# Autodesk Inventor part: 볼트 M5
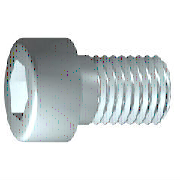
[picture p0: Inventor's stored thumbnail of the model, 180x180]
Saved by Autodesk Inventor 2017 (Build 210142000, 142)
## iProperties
IsCustomPart: 1
Created: 2012-02
Part Number: 볼트 M5
Material: 강철, 연강
Description: 6각머리 태핑 나사
Document SubType Name: Modeling
Standard: KS B 1003
Designer: mduedu
Standards Organization: KS
Language: ko-KR
Size Designation: M 5 x 12
Categories: <MemberInstance><Categories><Category DisplayName="조임쇠" InternalName="e4da775c-781d-43d5-af7c-5136215cf5a6" Mnemonic="FSTN"><Category DisplayName="볼트" InternalN
Density: 1 g/cm^3
Appearance: 강철
Author: mduedu
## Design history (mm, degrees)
sketch "스케치1"
  geometry: L1 (-1.167, 0)-(12, 0); L2 (12, 0)-(12, 2.5); L3 (12, 2.5)-(2, 2.5); L4 (2, 2.5)-(1.509, 2.5); L5 (1.509, 2.5)-(0, 2.5); L6 (0, 2.5)-(0, 4.25); L7 (0, 4.25)-(-5, 4.25); L8 (-5, 4.25)-(-5, 2.309); L9 (-5, 2.309)-(-2.5, 2.309); L10 (-2.5, 2.309)-(-1.167, 0); L11 (-8.4, 0)-(15.4, 0) reference; L12 (0, -0.85)-(0, 5.1) reference; L13 (2, 2.5)-(0, 2.5)
  constraints: 22 end point, 6 parallel, 2 collinear, 2 perpendicular, 1 horizontal, 1 point on line
  dimensions: "d1" = 10 distance from line of L3.end L2 (= GEL); "d2" = 0.49086 distance of L4.end L3.end (computed from GAL); "d3" = 5 distance between parallel lines of L8 L6 (= KOH); "d4" = 2.5 distance of L8.end L9.end (= INTI); "d5" = 60 deg angle of L10 L1; "d6" = 5 diameter of L3 L1 (= GD); "d7" = 5 diameter of L5 L1 (= BDM); "d8" = 4.6188 diameter of L9 L1 (= 1.1547 x SW); "d9" = 8.5 diameter of L7 L1 (= KOD); "d26" = 12 distance between parallel lines of L12 L2 (= NLG)
revolve "본체" sketch "스케치1" stored, may be unused: angle "d10" = 90 deg
sketch "스케치2"
  geometry: L1 (0, -5.95)-(0, 5.95) reference; L2 (-5.95, 0)-(5.95, 0) reference; L3 (2.309, 0)-(1.155, -2); L4 (1.155, -2)-(-1.155, -2); L5 (-1.155, -2)-(-2.309, 0); L6 (-2.309, 0)-(-1.155, 2); L7 (-1.155, 2)-(1.155, 2); L8 (1.155, 2)-(2.309, 0); 2 further points
  constraints: 12 end point, 1 coincident, 1 horizontal alignment, 1 point on line, 12 other
extrude "슬롯" join sketch "스케치2" stored distance "d11" = 10; taper "d12" = 0 deg
workplane "Work Plane1"
fillet "Fillet2" dims "d30" = 0.1 (= R)
body "Solid1"
fillet "모깎기1" dims "d17" = 0.5 (= RR)
feature "스레드" dims "d13" = 10 (= GEL), "d14" = 0
chamfer "모따기1" distance "d15" = 0.49076 (= -0.5 x SPD + 0.5 x GD); stored, may be unused: second distance "d16" = 0.49076 (= GUL), angle "d27" = 45 deg
other parameters: "GD" = 5 (= NND) [user parameter; used in 2 equation terms], "NLG" = 12 [user parameter; used in 1 equation term], "GEL" = 10 [user parameter; used in 2 equation terms], "KOD" = 8.5 [user parameter; used in 1 equation term], "KOH" = 5 [user parameter; used in 1 equation term], "INTI" = 2.5 [user parameter; used in 1 equation term], "GAL" = 0.49076 (= 0.61345 x PTC) [user parameter; used in 1 equation term], "GUL" = 0.49076 (= 0.61345 x PTC) [user parameter; used in 1 equation term], "BDM" = 5 (= NND) [user parameter; used in 1 equation term], "SW" = 4 [user parameter; used in 2 equation terms], "RR" = 0.5 [user parameter; used in 1 equation term], "SPD" = 4.01848 (= NND - 1.2269 x PTC) [user parameter; used in 1 equation term], "d19" = 0, "d28" = 0, "d29" = 0, "R" = 0.1 [user parameter; used in 1 equation term], "PHH" = 0.2 [user parameter], "GD1" = 4.01848 (= THREADDIA - 1.2269 x PTC) [user parameter], "THREADDIA" = 5 [user parameter; used in 1 equation term], "FAWI" = 45 deg [user parameter], "TPU" = 12.5 (computed from PTC) [user parameter], "PTC" = 0.8 [user parameter; used in 5 equation terms], "NND" = 5 [user parameter; used in 3 equation terms], "TOA" = 30 deg [user parameter], "E0" = 4.62 (= 1.155 x SW) [user parameter]
